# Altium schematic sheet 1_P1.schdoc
size 307 x 218 mm; Symbol: Drawing-Symbol_A4; Device: Drawing-Symbol_A4; @Project Name: New Project_2026-05-24_21-45-30; @Page Count: 1; @Update Date: 2026-05-24; @Create Date: 2026-05-24; @Schematic Name: Schematic1; @Page No: 1; @Page Name: P1; Company: EasyEDA.com; Version: V1.0; Page Size: A4; @Create Time: 18:45:37; @Update Time: 21:45:37; Width: 1170; Height: 825; Region Start: 1; X Region Count: 6; Y Region Count: 4; Blade Width: 10; Title Block Position: 3; @Board Name: Board1
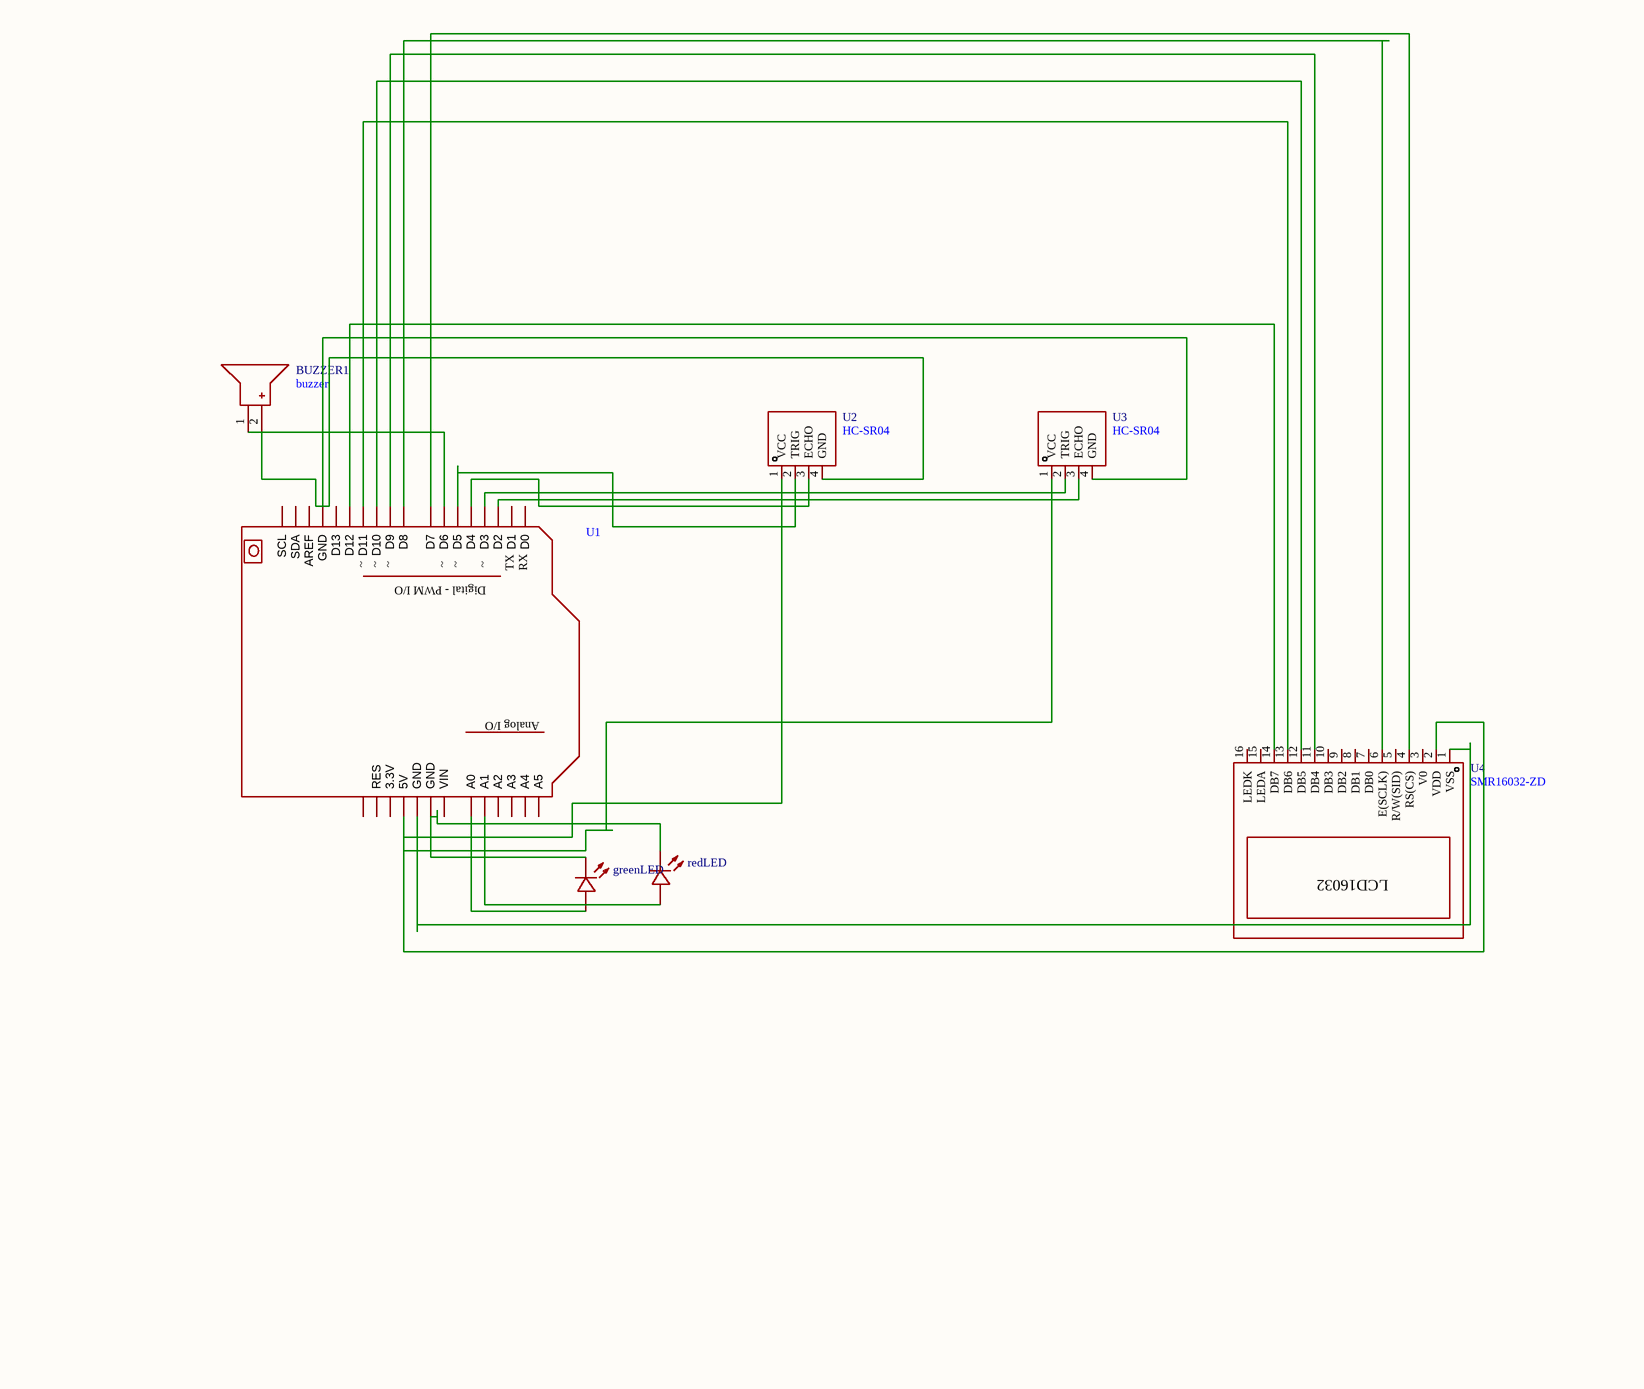
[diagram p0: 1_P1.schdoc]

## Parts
BUZZER1  buzzer  [BUZ-TH_BD12.0-P6.00-D0.9-RD]
greenLED  KT-0805G  [LED0805-R-RD]  (value not drawn)
redLED  KT-0805G  [LED0805-R-RD]  (value not drawn)
U1  (no value)  [ARDUINO UNO R3 FOOTPRINT]
U2  HC-SR04  [TH_HC-SR04V]
U3  HC-SR04  [TH_HC-SR04V]
U4  SMR16032-ZD  [LCD-TH_SMR16032-ZD]

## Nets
NetBUZZER1_1: BUZZER1.1(-) BUZZER1.2(+) U1.17(GND) U1.25(D6) U2.4(GND) U3.4(GND)
NetgreenLED_1: greenLED.1(A) U1.8(A0)
NetgreenLED_2: greenLED.2(K) redLED.2(K) U1.6(GND)
NetredLED_1: redLED.1(A) U1.9(A1)
NetU1_4: U1.4(5V) U2.1(VCC) U3.1(VCC) U4.2(VDD)
NetU1_5: U1.5(GND) U4.1(VSS)
NetU1_19: U1.19(D12) U4.14(DB7)
NetU1_20: U1.20(D11) U4.13(DB6)
NetU1_21: U1.21(D10) U4.12(DB5)
NetU1_22: U1.22(D9) U4.11(DB4)
NetU1_23: U1.23(D8) U4.6(E(SCLK))
NetU1_24: U1.24(D7) U4.4(RS(CS))
NetU1_26: U1.26(D5) U2.2(TRIG)
NetU1_27: U1.27(D4) U2.3(ECHO)
NetU1_28: U1.28(D3) U3.2(TRIG)
NetU1_29: U1.29(D2) U3.3(ECHO)

Not connected (* = marked no-connect by the designer): U1 1(blnk) 2(RES) 3(3.3V) 7(VIN) 10(A2) 11(A3) 12(A4) 13(A5) 14(SCL) 15(SDA) 16(AREF) 18(D13) 30(D1) 31(D0); U4 3(V0) 5(R/W(SID)) 7(DB0) 8(DB1) 9(DB2) 10(DB3) 15(LEDA) 16(LEDK)

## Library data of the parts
BUZZER1 = buzzer: Add into BOM: yes
greenLED redLED = KT-0805G: Manufacturer: KENTO; Symbol: 0805G (Green); Add into BOM: yes; Lamp Holder Type: 2mm x 1.25mm square LED; Illumination Color: Emerald Green; Voltage - Forward(Vf): 2.6V~3.1V; Power(Watts): 100mW; Forward Current: 5mA; Wavelength - Dominant: 513nm~528nm; Peak Wavelength: 525nm; Diode Configuration: Discrete Diode; Lens Color: Water Clear; Luminous Intensity: 430mcd; Viewing Angle: 120°
U1 = Arduino Uno: Add into BOM: yes
U2 U3 = HC-SR04: Manufacturer: Universal Microelectronics; Add into BOM: yes
U4 = SMR16032-ZD: Add into BOM: yes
